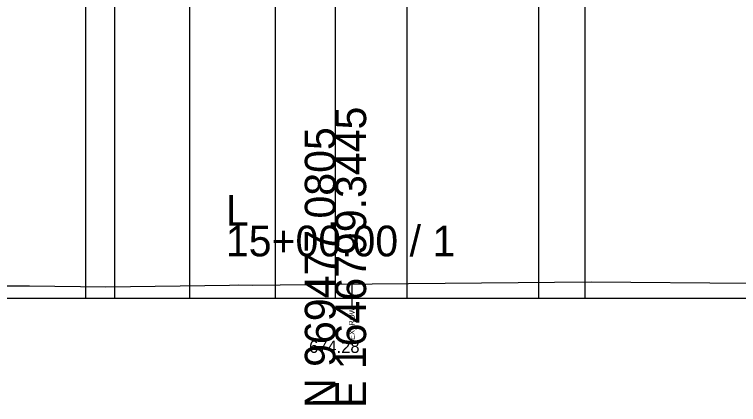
# Model space of a CAD drawing. Extents: x -26 to 2611564, y -962368 to 969476.
# Drawn here: x 70.7 to 136.8, y 4990.3 to 5025.9 of the extents above; entities that cross this region are included whole.
import ezdxf

# ---------------------------------------------------------------- set-up
doc = ezdxf.new("R2010")
doc.units = 0
for name, color, linetype in [('Exist Cross Section Cell', 7, 'Continuous'), ('Exist XS Center Line Elevation Label', 7, 'Continuous'), ('Exist XS Ground Line', 7, 'Continuous'), ('Pattern 5', 7, 'Continuous'), ('Scratch_Level_6', 7, 'Continuous')]:
    doc.layers.add(name, color=color, linetype=linetype)

msp = doc.modelspace()

# ---------------------------------------------------------------- linework, layer by layer
at = {"layer": 'Exist Cross Section Cell'}
for p, q in [((100, 5000), (100, 5006.627)), ((0, 5000), (100, 5000)), ((100, 5000), (200, 5000))]:
    msp.add_line(p, q, dxfattribs=at)
at = {"layer": 'Exist XS Ground Line'}
msp.add_lwpolyline([(0, 5000.92), (23.725, 5001.134), (33.576, 5001.3), (45.075, 5001.125), (59.75, 5001.127), (72.073, 5001.149), (79.039, 5001.045), (90.316, 5001.204), (91.113, 5001.216), (92.441, 5001.209), (100, 5001.277), (123.343, 5001.49), (137.788, 5001.371), (153.194, 5001.539), (157.525, 5001.662), (172.115, 5001.921), (177.606, 5001.963), (196.166, 5002.141), (200, 5002.209)], dxfattribs=at)
at = {"layer": 'Pattern 5'}
msp.add_line((101.5, 5001.291), (101.5, 4999.291), dxfattribs=at)
at = {"layer": 'Scratch_Level_6'}
for p, q in [((77.208, 5000), (77.208, 5061.485)), ((79.875, 5000), (79.875, 5061.485)), ((86.708, 5000), (86.708, 5061.485)), ((94.542, 5000), (94.542, 5061.485)), ((100, 5000), (100, 5061.485)), ((106.542, 5000), (106.542, 5061.485)), ((118.542, 5000), (118.542, 5061.485)), ((122.792, 5000), (122.792, 5061.485))]:
    msp.add_line(p, q, dxfattribs=at)

# ---------------------------------------------------------------- texts
at = {"layer": 'Exist Cross Section Cell'}
for s, p in [('E 1646799.3445', (102.8, 4990)), ('N 969477.0805', (100, 4990))]:
    msp.add_text(s, height=2.8, rotation=90, dxfattribs=at).set_placement(p)
for s, p in [('L', (90, 5006.627)), ('15+00.00 / 1', (90, 5003.827))]:
    msp.add_text(s, height=2.8, dxfattribs=at).set_placement(p)
at = {"layer": 'Exist XS Center Line Elevation Label'}
msp.add_text('674.28', height=1.125, dxfattribs=at).set_placement((97.596, 4995.016))
at = {"layer": 'Pattern 5'}
msp.add_text('EX_ROW', height=0.5, rotation=90, dxfattribs=at).set_placement((101.75, 4996.191))

doc.saveas('drawing.dxf')
